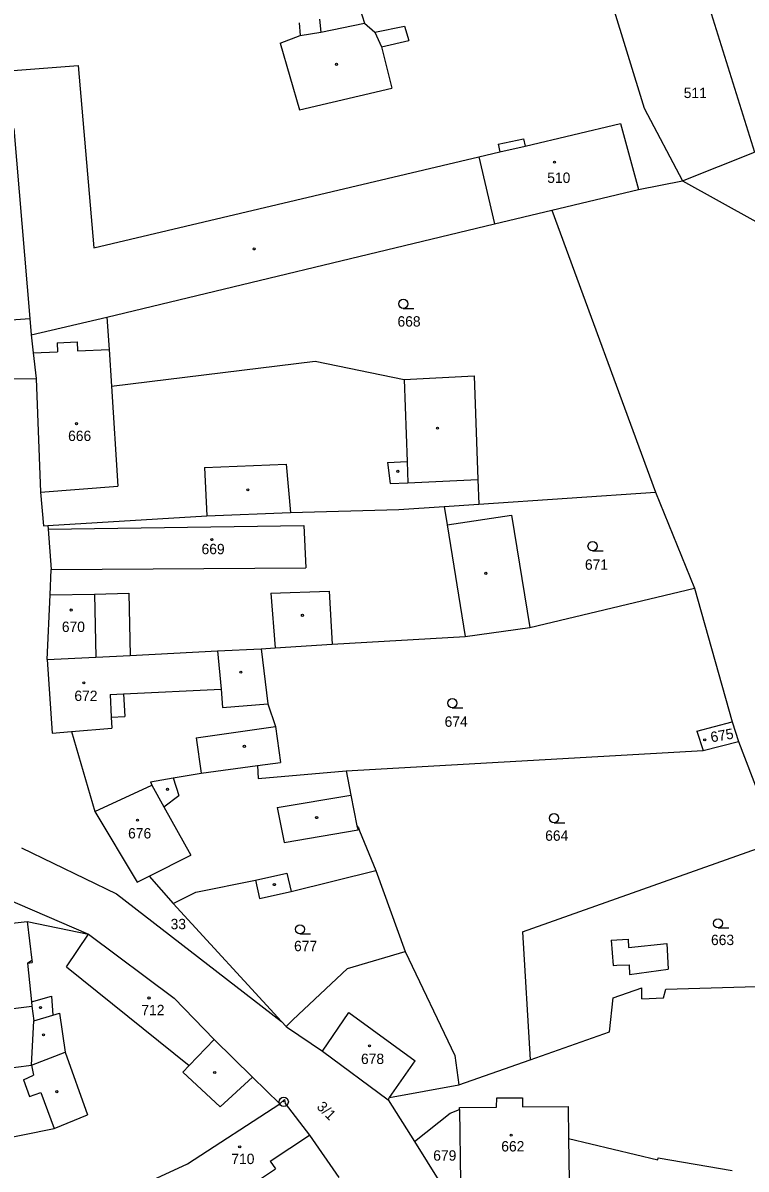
# Model space of a CAD drawing. Extents: x -779596 to -776743, y -1030330 to -1024513.
# Drawn here: x -777822.3 to -777703.6, y -1025045.8 to -1024857.5 of the extents above; entities that cross this region are included whole.
import ezdxf

# ---------------------------------------------------------------- set-up
doc = ezdxf.new("R2010")
doc.units = 0
for name, color, linetype in [('hranice parcel', 7, 'Continuous'), ('hranice vnitřní', 7, 'Continuous'), ('kultura', 7, 'Continuous'), ('Kód', 7, 'Continuous'), ('č_ parcel šipka', 7, 'Continuous'), ('č_pacel stav_', 7, 'Continuous'), ('č_parcel poz_', 7, 'Continuous')]:
    doc.layers.add(name, color=color, linetype=linetype)

msp = doc.modelspace()

# ---------------------------------------------------------------- linework, layer by layer
at = {"layer": 'hranice parcel'}
for points in [[(-777711.2, -1024849.74), (-777702.18, -1024878.71)], [(-777725.66, -1024854.1), (-777720.3, -1024871.5)], [(-777720.3, -1024871.5), (-777713.98, -1024883.42)], [(-777823.8, -1024874.86), (-777821.19, -1024906.04)], [(-777739.84, -1024877.71), (-777724.16, -1024874.01)], [(-777724.16, -1024874.01), (-777721.24, -1024884.83)], [(-777744.27, -1024877.38), (-777740.09, -1024876.53)], [(-777740.09, -1024876.53), (-777739.84, -1024877.71)], [(-777744.27, -1024877.38), (-777743.99, -1024878.69)], [(-777747.45, -1024879.51), (-777743.99, -1024878.69)], [(-777747.45, -1024879.51), (-777744.85, -1024890.5)], [(-777713.98, -1024883.42), (-777702.18, -1024878.71)], [(-777721.24, -1024884.83), (-777713.98, -1024883.42)], [(-777713.98, -1024883.42), (-777695.93, -1024893.43)], [(-777735.44, -1024888.24), (-777721.24, -1024884.83)], [(-777744.85, -1024890.5), (-777735.44, -1024888.24)], [(-777735.44, -1024888.24), (-777718.45, -1024934.58)], [(-777808.5, -1024905.81), (-777744.85, -1024890.5)], [(-777829.68, -1024906.66), (-777821.19, -1024906.04)], [(-777821.19, -1024906.04), (-777820.96, -1024908.76)], [(-777820.96, -1024908.76), (-777808.5, -1024905.81)], [(-777808.5, -1024905.81), (-777808.16, -1024911.14)], [(-777820.96, -1024908.76), (-777820.61, -1024911.68)], [(-777820.61, -1024911.68), (-777820.1, -1024915.91)], [(-777808.16, -1024911.14), (-777807.78, -1024917.15)], [(-777807.78, -1024917.15), (-777774.3, -1024913.05)], [(-777774.3, -1024913.05), (-777759.71, -1024916.09)], [(-777829.54, -1024915.94), (-777820.1, -1024915.91)], [(-777820.1, -1024915.91), (-777819.39, -1024934.58)], [(-777759.71, -1024916.09), (-777748.21, -1024915.5)], [(-777748.21, -1024915.5), (-777747.61, -1024932.5)], [(-777747.61, -1024932.5), (-777747.47, -1024936.55)], [(-777819.39, -1024934.58), (-777818.92, -1024940.13)], [(-777747.47, -1024936.55), (-777718.45, -1024934.58)], [(-777718.45, -1024934.58), (-777712.05, -1024950.37)], [(-777760.58, -1024937.43), (-777753.16, -1024936.93)], [(-777753.16, -1024936.93), (-777747.47, -1024936.55)], [(-777753.16, -1024936.93), (-777752.66, -1024939.95)], [(-777818.19, -1024940.09), (-777792.11, -1024938.48)], [(-777792.11, -1024938.48), (-777778.38, -1024937.93)], [(-777778.38, -1024937.93), (-777760.58, -1024937.43)], [(-777752.66, -1024939.95), (-777742.07, -1024938.39)], [(-777742.07, -1024938.39), (-777739.08, -1024956.83)], [(-777818.92, -1024940.13), (-777818.19, -1024940.09)], [(-777818.19, -1024940.09), (-777818.15, -1024940.69)], [(-777818.15, -1024940.69), (-777817.67, -1024947.32)], [(-777817.85, -1024951.47), (-777817.67, -1024947.32)], [(-777818.31, -1024962.08), (-777817.85, -1024951.47)], [(-777817.85, -1024951.47), (-777810.56, -1024951.33)], [(-777810.56, -1024951.33), (-777804.91, -1024951.21)], [(-777804.91, -1024951.21), (-777804.67, -1024961.4)], [(-777739.08, -1024956.83), (-777712.05, -1024950.37)], [(-777712.05, -1024950.37), (-777705.87, -1024972.35)], [(-777749.66, -1024958.31), (-777739.08, -1024956.83)], [(-777780.88, -1024960.15), (-777771.5, -1024959.54)], [(-777771.5, -1024959.54), (-777749.66, -1024958.31)], [(-777810.35, -1024961.68), (-777804.67, -1024961.4)], [(-777804.67, -1024961.4), (-777790.36, -1024960.67)], [(-777790.36, -1024960.67), (-777783.18, -1024960.31)], [(-777783.18, -1024960.31), (-777780.88, -1024960.15)], [(-777783.18, -1024960.31), (-777782.08, -1024969.38)], [(-777818.31, -1024962.08), (-777810.35, -1024961.68)], [(-777818.31, -1024962.08), (-777817.49, -1024974.19)], [(-777782.08, -1024969.38), (-777780.81, -1024973.07)], [(-777711.63, -1024973.88), (-777705.87, -1024972.35)], [(-777705.87, -1024972.35), (-777704.82, -1024975.57)], [(-777817.49, -1024974.19), (-777814.3, -1024973.93)], [(-777814.3, -1024973.93), (-777810.49, -1024987.04)], [(-777780.81, -1024973.07), (-777780.03, -1024979)], [(-777711.63, -1024973.88), (-777710.63, -1024977.06)], [(-777710.63, -1024977.06), (-777704.82, -1024975.57)], [(-777704.82, -1024975.57), (-777701.32, -1024984.69)], [(-777769.23, -1024980.39), (-777710.63, -1024977.06)], [(-777793.03, -1024980.78), (-777783.76, -1024979.51)], [(-777783.76, -1024979.51), (-777780.03, -1024979)], [(-777783.76, -1024979.51), (-777783.7, -1024981.65)], [(-777801.35, -1024982.18), (-777797.63, -1024981.55)], [(-777801.35, -1024982.18), (-777801.13, -1024982.74)], [(-777797.63, -1024981.55), (-777793.03, -1024980.78)], [(-777783.7, -1024981.65), (-777769.23, -1024980.39)], [(-777769.23, -1024980.39), (-777768.45, -1024984.39)], [(-777810.49, -1024987.04), (-777801.13, -1024982.74)], [(-777768.45, -1024984.39), (-777767.47, -1024989.39)], [(-777810.49, -1024987.04), (-777803.54, -1024998.68)], [(-777767.47, -1024989.39), (-777767.2, -1024989.74)], [(-777767.2, -1024989.74), (-777767.01, -1024990.21)], [(-777767.01, -1024990.21), (-777764.33, -1024996.75)], [(-777822.56, -1024993.01), (-777806.92, -1025000.57)], [(-777740.28, -1025006.85), (-777699.06, -1024992.22)], [(-777778.27, -1025000.18), (-777764.33, -1024996.75)], [(-777764.33, -1024996.75), (-777759.56, -1025010.05)], [(-777803.54, -1024998.68), (-777801.59, -1024997.7)], [(-777801.59, -1024997.7), (-777797.61, -1025002.15)], [(-777793.89, -1025000.33), (-777784.13, -1024998.36)], [(-777784.13, -1024998.36), (-777783.44, -1025001.37)], [(-777827.68, -1025000.26), (-777811.54, -1025007.24)], [(-777806.92, -1025000.57), (-777779.82, -1025021.56)], [(-777797.61, -1025002.15), (-777793.89, -1025000.33)], [(-777783.44, -1025001.37), (-777778.27, -1025000.18)], [(-777797.61, -1025002.15), (-777779.82, -1025021.56)], [(-777828.56, -1025005.89), (-777821.59, -1025005.14)], [(-777821.59, -1025005.14), (-777820.81, -1025011.49)], [(-777821.59, -1025005.14), (-777811.54, -1025007.24)], [(-777811.54, -1025007.24), (-777797.46, -1025017.74)], [(-777740.28, -1025006.85), (-777739.02, -1025027.87)], [(-777769.02, -1025012.85), (-777759.56, -1025010.05)], [(-777759.56, -1025010.05), (-777751.39, -1025027.15)], [(-777821.55, -1025011.98), (-777820.81, -1025011.49)], [(-777821.55, -1025011.98), (-777820.89, -1025018.35)], [(-777777.96, -1025021.31), (-777769.02, -1025012.85)], [(-777725.4, -1025017.7), (-777720.68, -1025016.06)], [(-777720.69, -1025017.86), (-777720.68, -1025016.06)], [(-777716.72, -1025016.24), (-777701.85, -1025015.8)], [(-777797.46, -1025017.74), (-777790.89, -1025024.52)], [(-777726.01, -1025023.29), (-777725.4, -1025017.7)], [(-777720.69, -1025017.86), (-777717.13, -1025017.68)], [(-777717.13, -1025017.68), (-777716.72, -1025016.24)], [(-777820.89, -1025018.35), (-777820.82, -1025019.05)], [(-777820.82, -1025019.05), (-777820.52, -1025021.47)], [(-777820.87, -1025028.74), (-777820.52, -1025021.47)], [(-777779.82, -1025021.56), (-777779.09, -1025022.39)], [(-777779.09, -1025022.39), (-777777.96, -1025021.31)], [(-777779.09, -1025022.39), (-777778.84, -1025022.56)], [(-777778.84, -1025022.56), (-777773.13, -1025026.46)], [(-777739.02, -1025027.87), (-777726.01, -1025023.29)], [(-777790.89, -1025024.52), (-777784.58, -1025030.72)], [(-777773.13, -1025026.46), (-777762.32, -1025034.41)], [(-777751.39, -1025027.15), (-777750.72, -1025031.99)], [(-777828.65, -1025029.71), (-777820.87, -1025028.74)], [(-777820.87, -1025028.74), (-777820.54, -1025030.39)], [(-777750.72, -1025031.99), (-777739.02, -1025027.87)], [(-777822.21, -1025031.15), (-777820.54, -1025030.39)], [(-777822.21, -1025031.15), (-777821.2, -1025033.91)], [(-777784.58, -1025030.72), (-777780.1, -1025035.12)], [(-777762.09, -1025034.08), (-777750.72, -1025031.99)], [(-777821.2, -1025033.91), (-777819.38, -1025033.24)], [(-777819.38, -1025033.24), (-777817.19, -1025039.17)], [(-777780.1, -1025035.12), (-777779.36, -1025034.36)], [(-777779.36, -1025034.36), (-777779.22, -1025035.04)], [(-777762.32, -1025034.41), (-777762.09, -1025034.08)], [(-777762.32, -1025034.41), (-777757.98, -1025041.28)], [(-777795.29, -1025044.96), (-777780.1, -1025035.12)], [(-777779.22, -1025035.04), (-777775.27, -1025040.23)], [(-777757.98, -1025041.28), (-777752.16, -1025036.63)], [(-777752.16, -1025036.63), (-777750.64, -1025036.01)], [(-777750.64, -1025036.01), (-777750.46, -1025047.94)], [(-777838.05, -1025043.34), (-777817.19, -1025039.17)], [(-777775.27, -1025040.23), (-777770.45, -1025047.21)], [(-777757.98, -1025041.28), (-777753.87, -1025047.97)], [(-777800.37, -1025047.3), (-777795.29, -1025044.96)]]:
    msp.add_lwpolyline(points, dxfattribs=at)
at = {"layer": 'hranice vnitřní'}
for points in [[(-777766.98, -1024855.11), (-777766.21, -1024857.52)], [(-777776.93, -1024857.45), (-777776.76, -1024859.54)], [(-777773.6, -1024856.89), (-777773.4, -1024858.99)], [(-777773.4, -1024858.99), (-777766.21, -1024857.52)], [(-777766.21, -1024857.52), (-777764.53, -1024859.02)], [(-777780.06, -1024860.83), (-777776.76, -1024859.54)], [(-777776.76, -1024859.54), (-777773.4, -1024858.99)], [(-777764.53, -1024859.02), (-777759.64, -1024858.01)], [(-777764.53, -1024859.02), (-777763.42, -1024861.44)], [(-777759.64, -1024858.01), (-777758.96, -1024860.35)], [(-777780.06, -1024860.83), (-777776.88, -1024871.76)], [(-777763.42, -1024861.44), (-777758.96, -1024860.35)], [(-777763.42, -1024861.44), (-777761.72, -1024868.21)], [(-777824.6, -1024865.35), (-777813.22, -1024864.48)], [(-777813.22, -1024864.48), (-777810.68, -1024894.46)], [(-777776.88, -1024871.76), (-777761.72, -1024868.21)], [(-777743.99, -1024878.69), (-777739.84, -1024877.71)], [(-777810.68, -1024894.46), (-777747.45, -1024879.51)], [(-777816.7, -1024910.06), (-777813.4, -1024909.89)], [(-777816.7, -1024910.06), (-777816.63, -1024911.51)], [(-777813.4, -1024909.89), (-777813.34, -1024911.36)], [(-777820.61, -1024911.68), (-777816.63, -1024911.51)], [(-777813.34, -1024911.36), (-777808.16, -1024911.14)], [(-777759.71, -1024916.09), (-777759.23, -1024929.57)], [(-777807.78, -1024917.15), (-777806.73, -1024933.63)], [(-777792.47, -1024930.53), (-777779.07, -1024929.99)], [(-777792.47, -1024930.53), (-777792.11, -1024938.48)], [(-777779.07, -1024929.99), (-777778.38, -1024937.93)], [(-777762.45, -1024929.7), (-777759.23, -1024929.57)], [(-777762.45, -1024929.7), (-777762.02, -1024933.16)], [(-777759.23, -1024929.57), (-777759.11, -1024933.03)], [(-777762.02, -1024933.16), (-777759.11, -1024933.03)], [(-777759.11, -1024933.03), (-777747.61, -1024932.5)], [(-777819.39, -1024934.58), (-777806.73, -1024933.63)], [(-777818.15, -1024940.69), (-777776.15, -1024940.07)], [(-777776.15, -1024940.07), (-777775.83, -1024947.03)], [(-777752.66, -1024939.95), (-777749.66, -1024958.31)], [(-777817.67, -1024947.32), (-777775.83, -1024947.03)], [(-777810.56, -1024951.33), (-777810.35, -1024961.68)], [(-777781.61, -1024951.2), (-777772.03, -1024950.85)], [(-777781.61, -1024951.2), (-777780.88, -1024960.15)], [(-777772.03, -1024950.85), (-777771.5, -1024959.54)], [(-777790.36, -1024960.67), (-777789.76, -1024966.94)], [(-777805.77, -1024967.75), (-777789.76, -1024966.94)], [(-777789.76, -1024966.94), (-777789.52, -1024969.97)], [(-777807.99, -1024967.86), (-777805.77, -1024967.75)], [(-777807.99, -1024967.86), (-777807.8, -1024971.54)], [(-777805.77, -1024967.75), (-777805.55, -1024971.43)], [(-777789.52, -1024969.97), (-777782.08, -1024969.38)], [(-777807.8, -1024971.54), (-777805.55, -1024971.43)], [(-777807.8, -1024971.54), (-777807.7, -1024973.39)], [(-777814.3, -1024973.93), (-777807.7, -1024973.39)], [(-777793.85, -1024974.96), (-777780.81, -1024973.07)], [(-777793.85, -1024974.96), (-777793.03, -1024980.78)], [(-777797.63, -1024981.55), (-777796.71, -1024984.44)], [(-777801.13, -1024982.74), (-777799.16, -1024986.27)], [(-777799.16, -1024986.27), (-777796.71, -1024984.44)], [(-777780.57, -1024986.4), (-777768.45, -1024984.39)], [(-777799.16, -1024986.27), (-777794.72, -1024994.22)], [(-777780.57, -1024986.4), (-777779.41, -1024992.14)], [(-777767.47, -1024989.39), (-777767.26, -1024990.05)], [(-777779.41, -1024992.14), (-777767.26, -1024990.05)], [(-777801.59, -1024997.7), (-777794.72, -1024994.22)], [(-777784.13, -1024998.36), (-777778.96, -1024997.17)], [(-777778.96, -1024997.17), (-777778.27, -1025000.18)], [(-777815.15, -1025012.58), (-777811.54, -1025007.24)], [(-777725.74, -1025008.18), (-777722.95, -1025008.05)], [(-777725.74, -1025008.18), (-777725.38, -1025012.35)], [(-777722.95, -1025008.05), (-777722.89, -1025009.38)], [(-777722.89, -1025009.38), (-777716.57, -1025008.77)], [(-777716.57, -1025008.77), (-777716.33, -1025012.96)], [(-777821.55, -1025011.98), (-777820.77, -1025011.88)], [(-777820.81, -1025011.49), (-777820.77, -1025011.88)], [(-777725.38, -1025012.35), (-777724.81, -1025012.32)], [(-777724.81, -1025012.32), (-777722.76, -1025012.23)], [(-777722.76, -1025012.23), (-777722.69, -1025013.85)], [(-777815.15, -1025012.58), (-777795, -1025028.8)], [(-777722.69, -1025013.85), (-777716.33, -1025012.96)], [(-777820.89, -1025018.35), (-777817.6, -1025017.43)], [(-777817.6, -1025017.43), (-777817.41, -1025020.53)], [(-777826.97, -1025019.82), (-777820.82, -1025019.05)], [(-777820.52, -1025021.47), (-777817.41, -1025020.53)], [(-777817.41, -1025020.53), (-777816.32, -1025020.19)], [(-777816.32, -1025020.19), (-777815.38, -1025026.58)], [(-777773.13, -1025026.46), (-777768.81, -1025020.11)], [(-777768.81, -1025020.11), (-777757.9, -1025028.04)], [(-777795, -1025028.8), (-777790.89, -1025024.52)], [(-777820.87, -1025028.74), (-777815.38, -1025026.58)], [(-777815.38, -1025026.58), (-777811.7, -1025036.92)], [(-777796.04, -1025029.88), (-777795, -1025028.8)], [(-777762.09, -1025034.08), (-777757.9, -1025028.04)], [(-777796.04, -1025029.88), (-777789.92, -1025035.57)], [(-777789.92, -1025035.57), (-777784.58, -1025030.72)], [(-777744.52, -1025035.63), (-777744.49, -1025034.1)], [(-777744.49, -1025034.1), (-777740.28, -1025034.12)], [(-777740.28, -1025034.12), (-777740.25, -1025035.6)], [(-777750.64, -1025035.67), (-777744.52, -1025035.63)], [(-777750.64, -1025036.01), (-777750.64, -1025035.67)], [(-777740.25, -1025035.6), (-777732.8, -1025035.54)], [(-777732.8, -1025035.54), (-777732.72, -1025040.79)], [(-777817.19, -1025039.17), (-777811.7, -1025036.92)], [(-777781.73, -1025044.52), (-777775.27, -1025040.23)], [(-777732.72, -1025040.79), (-777718.03, -1025044.28)], [(-777732.72, -1025040.79), (-777732.62, -1025047.69)], [(-777718.03, -1025044.28), (-777717.98, -1025043.98)], [(-777717.98, -1025043.98), (-777705.86, -1025046.07)], [(-777784.28, -1025048.08), (-777780.84, -1025045.78)], [(-777781.73, -1025044.52), (-777780.84, -1025045.78)]]:
    msp.add_lwpolyline(points, dxfattribs=at)
at = {"layer": 'kultura'}
for points in [[(-777759.84, -1024904.39), (-777758.09, -1024904.39)], [(-777728.77, -1024944.21), (-777727.02, -1024944.21)], [(-777751.81, -1024970.01), (-777750.06, -1024970.01)], [(-777735.09, -1024988.9), (-777733.34, -1024988.9)], [(-777708.16, -1025006.19), (-777706.41, -1025006.19)], [(-777776.82, -1025007.17), (-777775.07, -1025007.17)]]:
    msp.add_lwpolyline(points, dxfattribs=at)
for centre, radius in [((-777770.81, -1024864.3), 0.175), ((-777735.02, -1024880.37), 0.175), ((-777784.32, -1024894.62), 0.175), ((-777759.84, -1024903.64), 0.75), ((-777813.49, -1024923.33), 0.175), ((-777754.22, -1024924.06), 0.175), ((-777760.74, -1024931.16), 0.175), ((-777785.37, -1024934.2), 0.175), ((-777791.27, -1024942.38), 0.175), ((-777728.77, -1024943.46), 0.75), ((-777746.3, -1024947.93), 0.175), ((-777814.38, -1024953.96), 0.175), ((-777776.41, -1024954.82), 0.175), ((-777786.52, -1024964.17), 0.175), ((-777812.31, -1024965.91), 0.175), ((-777751.81, -1024969.26), 0.75), ((-777785.94, -1024976.35), 0.175), ((-777710.35, -1024975.28), 0.175), ((-777798.56, -1024983.42), 0.175), ((-777774.07, -1024988.06), 0.175), ((-777735.09, -1024988.15), 0.75), ((-777803.48, -1024988.49), 0.175), ((-777781.02, -1024999.07), 0.175), ((-777708.16, -1025005.44), 0.75), ((-777776.82, -1025006.42), 0.75), ((-777801.59, -1025017.7), 0.175), ((-777819.41, -1025019.28), 0.175), ((-777818.92, -1025023.76), 0.175), ((-777765.39, -1025025.56), 0.175), ((-777790.81, -1025029.95), 0.175), ((-777816.74, -1025033.1), 0.175), ((-777742.14, -1025040.24), 0.175), ((-777786.71, -1025042.16), 0.175)]:
    msp.add_circle(centre, radius, dxfattribs=at)
at = {"layer": 'Kód'}
for radius in [0.75, 0.032]:
    msp.add_circle((-777779.47, -1025034.76), radius, dxfattribs=at)

# ---------------------------------------------------------------- texts
at = {"layer": 'č_ parcel šipka'}
msp.add_text('33', height=1.7, dxfattribs=at).set_placement((-777798.05, -1025006.4))
msp.add_text('3/1', height=1.7, rotation=315.00251, dxfattribs=at).set_placement((-777774.178, -1025035.7))
at = {"layer": 'č_pacel stav_'}
for s, p in [('510', (-777736.21, -1024883.77)), ('666', (-777814.88, -1024926.18)), ('669', (-777792.97, -1024944.78)), ('670', (-777815.91, -1024957.56)), ('672', (-777813.85, -1024968.9)), ('676', (-777805.03, -1024991.49)), ('712', (-777802.85, -1025020.53)), ('678', (-777766.79, -1025028.55)), ('662', (-777743.76, -1025042.92)), ('710', (-777788.08, -1025044.99))]:
    msp.add_text(s, height=1.7, dxfattribs=at).set_placement(p)
msp.add_text('675', height=1.7, rotation=9.90008, dxfattribs=at).set_placement((-777709.248, -1024975.709))
at = {"layer": 'č_parcel poz_'}
for s, p in [('511', (-777713.8, -1024869.83)), ('668', (-777760.8, -1024907.38)), ('671', (-777730.02, -1024947.34)), ('674', (-777753.06, -1024973.14)), ('664', (-777736.55, -1024991.87)), ('677', (-777777.78, -1025010.01)), ('663', (-777709.32, -1025009.01)), ('679', (-777754.93, -1025044.43))]:
    msp.add_text(s, height=1.7, dxfattribs=at).set_placement(p)

doc.saveas('drawing.dxf')
